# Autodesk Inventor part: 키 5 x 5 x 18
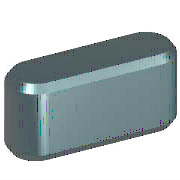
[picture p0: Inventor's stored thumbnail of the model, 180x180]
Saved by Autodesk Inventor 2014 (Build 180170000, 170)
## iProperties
Created: 2012-02
Part Number: 키 5 x 5 x 18
Material: 강철, 연강
Description: 키 및 해당 키홈
Document SubType Name: Modeling
Standard: KS B 1311
Designer: mduedu
Standards Organization: KS
Language: ko-KR
Size Designation: 5 x 5 x 18
Categories: <MemberInstance><Categories><Category DisplayName="샤프트 부품" InternalName="7f7aeb1f-a693-4053-b835-cee3144e0d98" Mnemonic="SHFT"><Category DisplayName="키" Interna
Density: 7.86 g/cm^3
Appearance: 매끄러움 - 노란색
Mass: 3.27476 g
Surface Area: 3.57848 cm^2
Volume: 0.416636 cm^3
IsCustomPart: 1
Author: mduedu
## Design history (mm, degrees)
workplane "Work Plane1"
workplane "Work Plane2"
sketch "스케치1"
  geometry: L1 (2.5, 2.5)-(15.5, 2.5); L2 (15.5, -2.5)-(2.5, -2.5); L3 (0, 9.4)-(0, -7.4) reference; L4 (-5, 0)-(30, 0) reference; L5 (18, 0)-(18, 7); A1 r 2.5 centre (2.5, 0) between (2.5, 2.5) and (2.5, -2.5); A2 r 2.5 centre (15.5, 0) between (15.5, -2.5) and (15.5, 2.5)
  constraints: 6 end point, 5 point on circle, 4 tangent, 3 point on line, 2 centre point, 1 horizontal, 1 parallel, 1 perpendicular
  dimensions: "d0" = 2.5 radius of A1 (= 0.5 x PB); "d13" = 2.5 radius of A2 (= 0.5 x PB); "d14" = 18 distance between parallel lines of L5 L3 (= NLG)
extrude "본체1" new body sketch "스케치1" taper "d3" = 0 deg; stored distance "d4" = 10
workplane "Work Plane3"
body "Solid1"
chamfer "모따기1" distance "d8" = 0.4 (= PHH); stored, may be unused: second distance "d9" = 0.4 (= PHH), angle "d15" = 45 deg
other parameters: "d1" = -3 (= -PNT), "d2" = 2 (= PH - PNT), "NLG" = 18 [user parameter; used in 3 equation terms], "PB" = 5 [user parameter; used in 2 equation terms], "PNT" = 3 [user parameter; used in 2 equation terms], "PH" = 5 [user parameter; used in 1 equation term], "PHH" = 0.4 [user parameter; used in 2 equation terms], "d10" = 0, "d16" = 0, "d17" = 0, "d18" = 0, "WDMIN" = 12 [user parameter], "PLB2" = 18 (= NLG) [user parameter], "WDMAX" = 17 [user parameter], "PLB1" = 18 (= NLG) [user parameter], "RR" = 0.16 [user parameter], "PUEB" = 2.3 [user parameter]
